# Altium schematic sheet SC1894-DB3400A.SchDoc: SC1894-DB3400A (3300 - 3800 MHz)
size B; Organization: Maxim Integrated; Address1: 160 Rio Robles; Address2: San Jose, CA. 95134; Address3: U.S.A.; Address4: 408-601-1000; Revision: 2.0; SheetNumber: 1; SheetTotal: 1; PageSetup: Record=PageOptions¦CenterHorizontal=True¦CenterVertical=True¦PrintScale=1.12¦XCorrection=1.00¦YCorrection=1.00¦PrintKind=1¦BorderSize=5000000¦LeftOffset=0¦BottomOffset=0¦Orientation=2¦PaperLength=1000¦PaperWidth=1000¦Scale=100¦PaperSource=15¦PrintQuality=600¦MediaType=1¦DitherType=10¦PaperKind=Tabloid¦PrintScaleMode=1
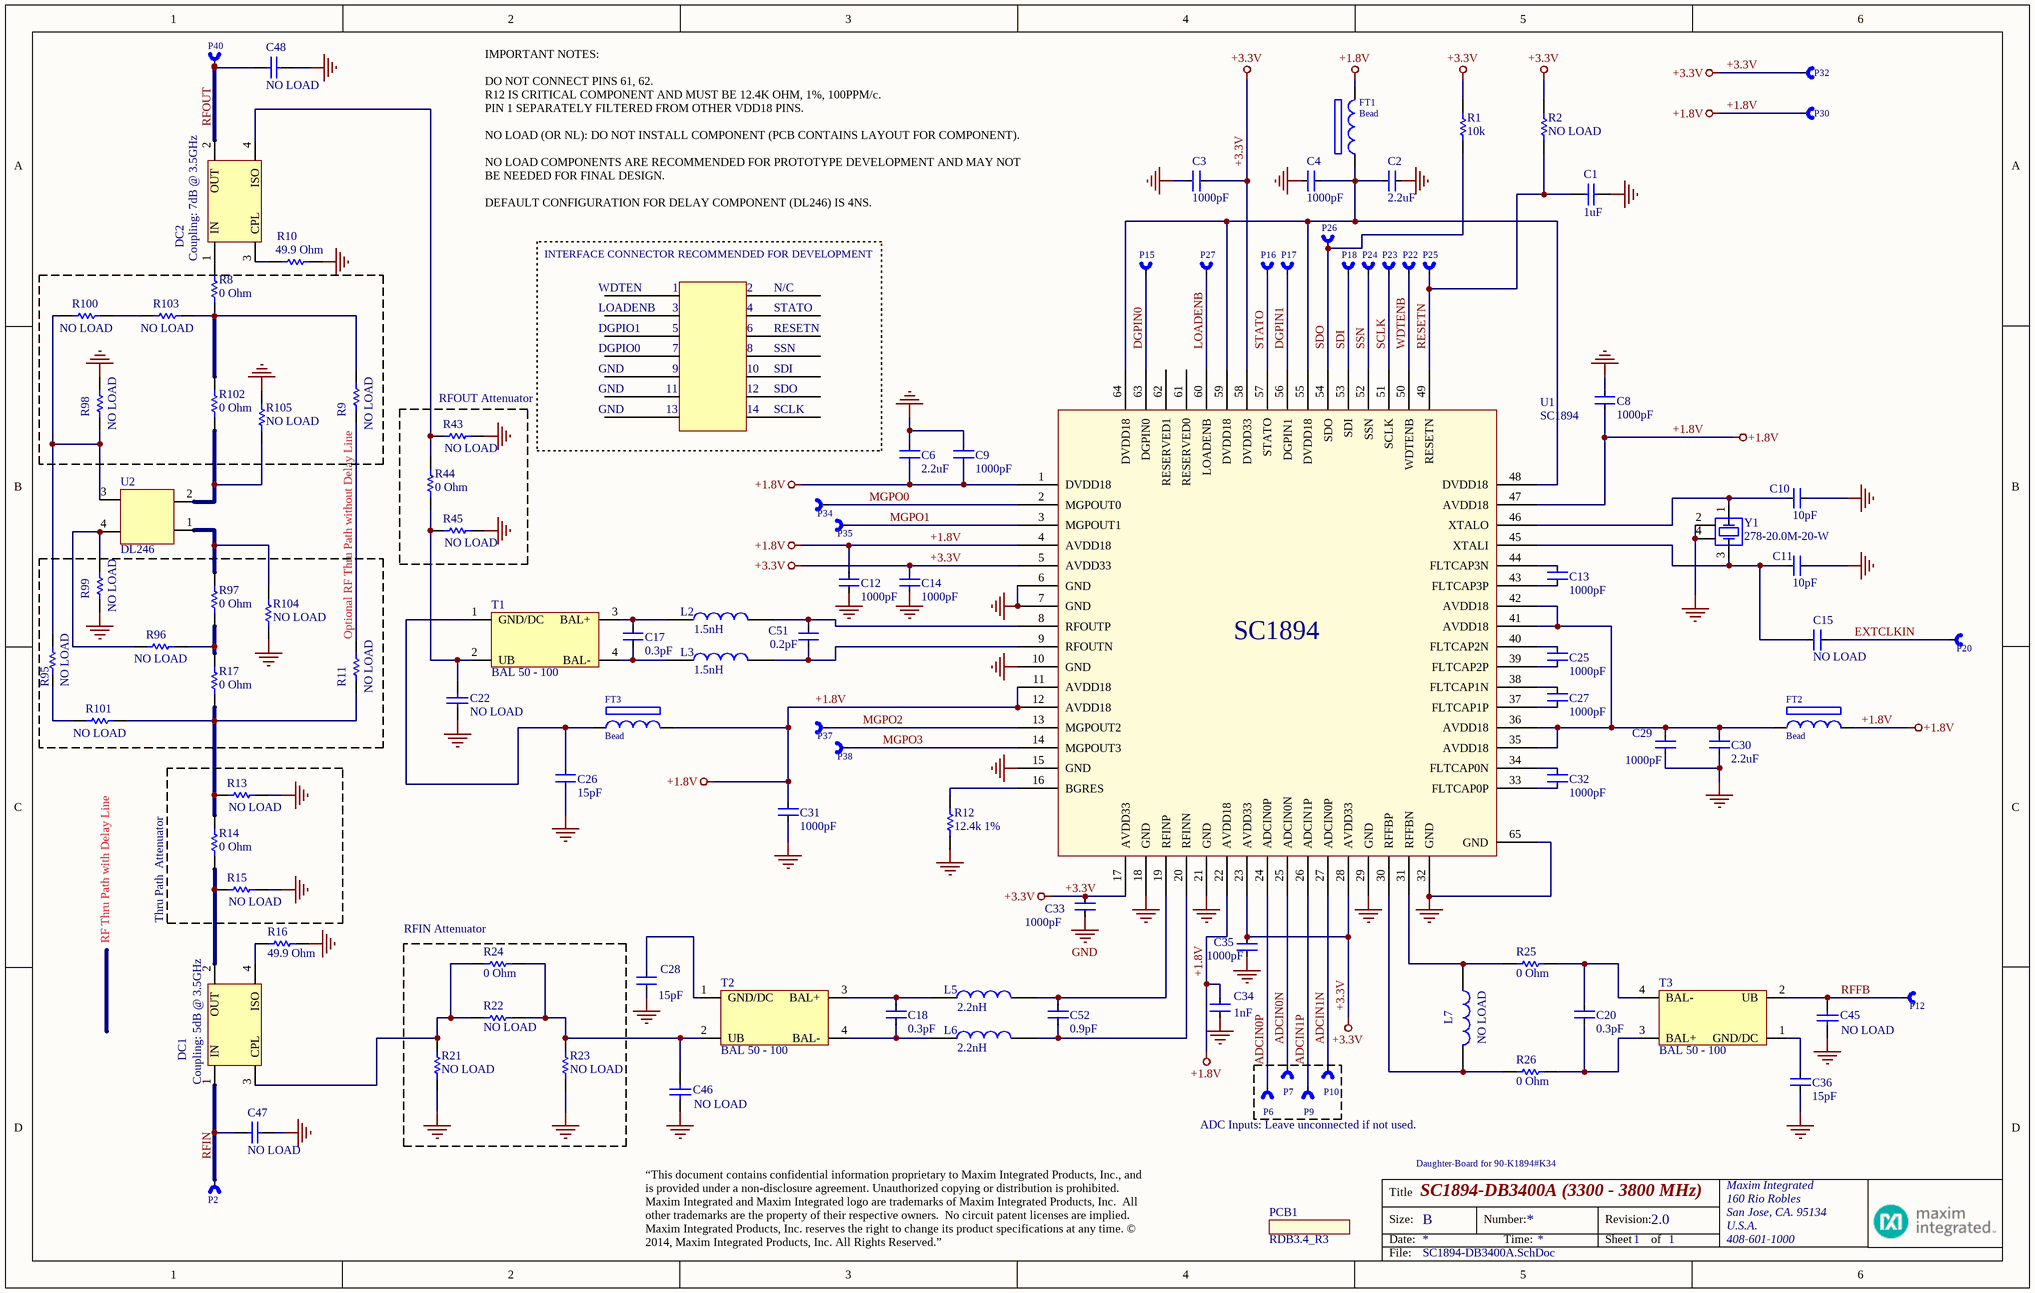
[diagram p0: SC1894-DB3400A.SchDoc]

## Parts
C1  1uF  [1608[0603]]
C2  2.2uF  [0603 SMD]
C3  1000pF  [0402 SMD]
C4  1000pF  [0402 SMD]
C6  2.2uF  [0603 SMD]
C8  1000pF  [0402 SMD]
C9  1000pF  [0402 SMD]
C10  10pF  [0402 SMD]
C11  10pF  [0402 SMD]
C12  1000pF  [0402 SMD]
C13  1000pF  [0402 SMD]
C14  1000pF  [0402 SMD]
C15  NO LOAD  [0402 SMD]
C17  0.3pF  [0402 SMD]
C18  0.3pF  [0402 SMD]
C20  0.3pF  [0402 SMD]
C22  NO LOAD  [0402 SMD]
C25  1000pF  [0402 SMD]
C26  15pF  [0402 SMD]
C27  1000pF  [0402 SMD]
C28  15pF  [0402 SMD]
C29  1000pF  [0402 SMD]
C30  2.2uF  [0603 SMD]
C31  1000pF  [0402 SMD]
C32  1000pF  [0402 SMD]
C33  1000pF  [0402 SMD]
C34  1nF  [0402 SMD]
C35  1000pF  [0402 SMD]
C36  15pF  [0402 SMD]
C45  NO LOAD  [0402 SMD]
C46  NO LOAD  [0402 SMD]
C47  NO LOAD  [0402 SMD]
C48  NO LOAD  [0402 SMD]
C51  0.2pF  [0402 SMD]
C52  0.9pF  [0402 SMD]
DC1  Coupling: 5dB @ 3.5GHz  [0603_AVX_LGA_COUPLER]
DC2  Coupling: 7dB @ 3.5GHz  [0603_AVX_LGA_COUPLER]
FT1  Bead  [0603 SMD]
FT2  Bead  [0603 SMD]
FT3  Bead  [0402 SMD]
L2  1.5nH  [0402 SMD]
L3  1.5nH  [0402 SMD]
L5  2.2nH  [0402 SMD]
L6  2.2nH  [0402 SMD]
L7  NO LOAD  [0402 SMD]
P2  PORT 1-M  [PORT-1_M-PAD]  (value not drawn)
P6  PORT 1-M  [PORT-1_M-PAD]  (value not drawn)
P7  PORT 1-M  [PORT-1_M-PAD]  (value not drawn)
P9  PORT 1-M  [PORT-1_M-PAD]  (value not drawn)
P10  PORT 1-M  [PORT-1_M-PAD]  (value not drawn)
P12  PORT 1-M  [PORT-1_M-PAD]  (value not drawn)
P15  PORT 1-M  [PORT-1_M-PAD]  (value not drawn)
P16  PORT 1-M  [PORT-1_M-PAD]  (value not drawn)
P17  PORT 1-M  [PORT-1_M-PAD]  (value not drawn)
P18  PORT 1-M  [PORT-1_M-PAD]  (value not drawn)
P20  PORT 1-M  [PORT-1_M-PAD]  (value not drawn)
P22  PORT 1-M  [PORT-1_M-PAD]  (value not drawn)
P23  PORT 1-M  [PORT-1_M-PAD]  (value not drawn)
P24  PORT 1-M  [PORT-1_M-PAD]  (value not drawn)
P25  PORT 1-M  [PORT-1_M-PAD]  (value not drawn)
P26  PORT 1-M  [PORT-1_M-PAD]  (value not drawn)
P27  PORT 1-M  [PORT-1_M-PAD]  (value not drawn)
P30  PORT 1-M  [PORT-1_M-PAD]  (value not drawn)
P32  PORT 1-M  [PORT-1_M-PAD]  (value not drawn)
P34  PORT 1-M  [PORT-1_M-PAD]  (value not drawn)
P35  PORT 1-M  [PORT-1_M-PAD]  (value not drawn)
P37  PORT 1-M  [PORT-1_M-PAD]  (value not drawn)
P38  PORT 1-M  [PORT-1_M-PAD]  (value not drawn)
P40  PORT 1-M  [PORT-1_M-PAD]  (value not drawn)
PCB1  RDB3.4_R3
R1  10k  [0402 SMD]
R2  NO LOAD  [0402 SMD]
R8  0 Ohm  [0402 SMD]
R9  NO LOAD  [0402 SMD]
R10  49.9 Ohm  [0402 SMD]
R11  NO LOAD  [0402 SMD]
R12  12.4k 1%  [0402 SMD]
R13  NO LOAD  [0402 SMD]
R14  0 Ohm  [0402 SMD]
R15  NO LOAD  [0402 SMD]
R16  49.9 Ohm  [0402 SMD]
R17  0 Ohm  [0402 SMD]
R21  NO LOAD  [0402 SMD]
R22  NO LOAD  [0201_SMT]
R23  NO LOAD  [0402 SMD]
R24  0 Ohm  [0201_SMT]
R25  0 Ohm  [0402 SMD]
R26  0 Ohm  [0402 SMD]
R43  NO LOAD  [0402 SMD]
R44  0 Ohm  [0402 SMD]
R45  NO LOAD  [0402 SMD]
R95  NO LOAD  [0402 SMD]
R96  NO LOAD  [0402 SMD]
R97  0 Ohm  [0402 SMD]
R98  NO LOAD  [0402 SMD]
R99  NO LOAD  [0402 SMD]
R100  NO LOAD  [0402 SMD]
R101  NO LOAD  [0402 SMD]
R102  0 Ohm  [0402 SMD]
R103  NO LOAD  [0402 SMD]
R104  NO LOAD  [0402 SMD]
R105  NO LOAD  [0402 SMD]
T1  BAL 50 - 100  [0404_Balun]
T2  BAL 50 - 100  [0404_Balun]
T3  BAL 50 - 100  [0404_Balun]
U1  SC1894  [SC1894]
U2  DL246  [DL246-A]
Y1  278-20.0M-20-W  [278-20.0M]

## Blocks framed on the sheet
RFOUT Attenuator: R43-R45
Optional RF Thru Path without Delay Line: R11 R17 R95-R97 R99 R101 R104
Thru Path  Attenuator: R13-R15
RFIN Attenuator: R21-R24

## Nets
+1.8V: C6.2 C8.2 C9.2 C12.1 C31.2 C34.2 FT1.2 FT2.2 FT3.2 P30.1(P*) U1.1(DVDD18) U1.4(AVDD18) U1.11(AVDD18) U1.12(AVDD18) U1.22(AVDD18) U1.47(AVDD18)
+3.3V: C3.2 C14.1 C33.1 C35.2 P32.1(P*) R1.2 R2.2 U1.5(AVDD33) U1.17(AVDD33) U1.23(AVDD33) U1.28(AVDD33) U1.58(DVDD33)
GND: C1.1 C2.2 C3.1 C4.1 C6.1 C8.1 C9.1 C10.2 C11.2 C12.2 C14.2 C22.1 C26.2 C28.2 C29.2 C30.2 C31.1 C33.2 C34.1 C35.1 C36.2 C45.1 C46.1 C47.1 C48.1 R10.2 R12.1 R13.2 R15.2 R16.2 R21.2 R23.2 R43.2 R45.2 R98.1 R99.2 R104.2 R105.1 U1.6(GND) U1.7(GND) U1.10(GND) U1.15(GND) U1.18(GND) U1.21(GND) U1.29(GND) U1.32(GND) U1.65(GND) Y1.2(SHIELD1) Y1.4(SHIELD2)
ADCIN0N: P7.1(P*) U1.25(ADCIN0N)
ADCIN0P: P6.1(P*) U1.24(ADCIN0P)
ADCIN1N: P10.1(P*) U1.27(ADCIN0P)
ADCIN1P: P9.1(P*) U1.26(ADCIN1P)
DGPIN0: P15.1(P*) U1.63(DGPIN0)
DGPIN1: P17.1(P*) U1.56(DGPIN1)
EXTCLKIN: C15.2 P20.1(P*)
LOADENB: P27.1(P*) U1.60(LOADENB)
MGPO0: P34.1(P*) U1.2(MGPOUT0)
MGPO1: P35.1(P*) U1.3(MGPOUT1)
MGPO2: P37.1(P*) U1.13(MGPOUT2)
MGPO3: P38.1(P*) U1.14(MGPOUT3)
RESETN: C1.2 P25.1(P*) R2.1 U1.49(RESETN)
RFFB: C45.2 P12.1(P*) T3.2(UB)
RFIN: C47.2 DC1.1(IN) P2.1(P*)
RFOUT: C48.2 DC2.2(OUT) P40.1(P*)
SCLK: P23.1(P*) U1.51(SCLK)
SDI: P18.1(P*) U1.53(SDI)
SDO: P26.1(P*) R1.1 U1.54(SDO)
SSN: P24.1(P*) U1.52(SSN)
STATO: P16.1(P*) U1.57(STATO)
WDTENB: P22.1(P*) U1.50(WDTENB)
NetC2_1: C2.1 C4.2 FT1.1 U1.48(DVDD18) U1.55(DVDD18) U1.59(DVDD18) U1.64(DVDD18)
NetC10_1: C10.1 U1.46(XTALO) Y1.1(OSC1)
NetC11_1: C11.1 C15.1 U1.45(XTALI) Y1.3(OSC2)
NetC13_1: C13.1 U1.44(FLTCAP3N)
NetC13_2: C13.2 U1.43(FLTCAP3P)
NetC17_1: C17.1 L2.1 T1.3(BAL+)
NetC17_2: C17.2 L3.1 T1.4(BAL-)
NetC18_1: C18.1 L5.1 T2.3(BAL+)
NetC18_2: C18.2 L6.1 T2.4(BAL-)
NetC20_1: C20.1 R25.2 T3.4(BAL-)
NetC20_2: C20.2 R26.2 T3.3(BAL+)
NetC22_2: C22.2 R44.1 R45.1 T1.2(UB)
NetC25_1: C25.1 U1.40(FLTCAP2N)
NetC25_2: C25.2 U1.39(FLTCAP2P)
NetC26_1: C26.1 FT3.1 T1.1(GND/DC)
NetC27_1: C27.1 U1.38(FLTCAP1N)
NetC27_2: C27.2 U1.37(FLTCAP1P)
NetC28_1: C28.1 T2.1(GND/DC)
NetC29_1: C29.1 C30.1 FT2.1 U1.35(AVDD18) U1.36(AVDD18) U1.41(AVDD18) U1.42(AVDD18)
NetC32_1: C32.1 U1.34(FLTCAP0N)
NetC32_2: C32.2 U1.33(FLTCAP0P)
NetC36_1: C36.1 T3.1(GND/DC)
NetC46_2: C46.2 R22.2 R23.1 R24.2 T2.2(UB)
NetC51_1: C51.1 L2.2 U1.8(RFOUTP)
NetC51_2: C51.2 L3.2 U1.9(RFOUTN)
NetC52_1: C52.1 L5.2 U1.19(RFINP)
NetC52_2: C52.2 L6.2 U1.20(RFINN)
NetDC1_2: DC1.2(OUT) R14.1 R15.1
NetDC1_3: DC1.3(CPL) R21.1 R22.1 R24.1
NetDC1_4: DC1.4(ISO) R16.1
NetDC2_1: DC2.1(IN) R8.2
NetDC2_3: DC2.3(CPL) R10.1
NetDC2_4: DC2.4(ISO) R43.1 R44.2
NetL7_1: L7.1 R25.1 U1.31(RFFBN)
NetL7_2: L7.2 R26.1 U1.30(RFFBP)
NetR8_1: R8.1 R9.2 R102.2 R103.2
NetR9_1: R9.1 R11.2
NetR11_1: R11.1 R13.1 R14.2 R17.1 R101.1
NetR12_2: R12.2 U1.16(BGRES)
NetR17_2: R17.2 R96.1 R97.1
NetR95_1: R95.1 R98.2 R100.1 U2.3(2ns_B)
NetR95_2: R95.2 R101.2
NetR96_2: R96.2 R99.1 U2.4(2ns_A)
NetR97_2: R97.2 R104.1 U2.1(4ns_A)
NetR100_2: R100.2 R103.1
NetR102_1: R102.1 R105.2 U2.2(4ns_B)

Not connected (* = marked no-connect by the designer): U1 61(RESERVED0) 62(RESERVED1)

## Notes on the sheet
- IMPORTANT NOTES:
  DO NOT CONNECT PINS 61, 62.
  R12 IS CRITICAL COMPONENT AND MUST BE 12.4K OHM, 1%, 100PPM/c.
  PIN 1 SEPARATELY FILTERED FROM OTHER VDD18 PINS.
  NO LOAD (OR NL): DO NOT INSTALL COMPONENT (PCB CONTAINS LAYOUT FOR COMPONENT).
  NO LOAD COMPONENTS ARE RECOMMENDED FOR PROTOTYPE DEVELOPMENT AND MAY NOT BE NEEDED FOR FINAL DESIGN.
  DEFAULT CONFIGURATION FOR DELAY COMPONENT (DL246) IS 4NS.
- INTERFACE CONNECTOR RECOMMENDED FOR DEVELOPMENT
- WDTEN
- 1
- 2
- N/C
- LOADENB
- DGPIO1
- DGPIO0
- GND
- 3
- 5
- 7
- 9
- 4
- 6
- 8
- 10
- STATO
- RESETN
- SSN
- SDI
- 11
- 13
- 12
- 14
- SDO
- SCLK
- (near R101) RF Thru Path with Delay Line
- ADC Inputs: Leave unconnected if not used.
- Daughter-Board for 90-K1894#K34
- “This document contains confidential information proprietary to Maxim Integrated Products, Inc., and is provided under a non-disclosure agreement. Unauthorized copying or distribution is prohibited.  Maxim Integrated and Maxim Integrated logo are trademarks of Maxim Integrated Products, Inc.  All other trademarks are the property of their respective owners.  No circuit patent licenses are implied.  Maxim Integrated Products, Inc. reserves the right to change its product specifications at any time. © 2014, Maxim Integrated Products, Inc. All Rights Reserved.”

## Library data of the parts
C1 = 1u: 1uF 0603 ceramic capacitor
C2 C6 C30 = Cap 2.2uF 0603: 2.2uF 0603
C3 C4 C8 C9 C12-C14 C25 C27 C29 C31-C35 = Cap 1000pF: 1000pF 0402
C10 C11 C15 = Cap 10pF: 10pF 0402
C17 C18 C20 = Cap 0.3pF: 0.3pF 0402; Part Substitution Allowed?: No
C22 C45-C48 = Capacitor: Generic Capacitor
C26 C28 C36 = Cap 15pF: 15pF 0402; Part Substitution Allowed?: No
C51 = Cap 0.2pF: 0.2pF 0402; Part Substitution Allowed?: No
C52 = Cap 0.9pF: 0.9pF 0402; Part Substitution Allowed?: No
DC1 = CP0603AxxxxCN: AVX 0603 Coupler C LGA Terminatioon
DC2 = CP0603AxxxxHN: AVX 0603 Coupler C LGA Terminatioon
FT1 FT2 = Bead 0603: Part Substitution Allowed?: No; Value: 120mH
FT3 = Bead 0402: Bead 0402 470 ohm; Part Substitution Allowed?: No; Value: 470mH
L2 L3 = 1.5nH: Part Substitution Allowed?: No
L5 L6 = 2.2nH: Part Substitution Allowed?: No
L7 = Inductor: SMT Inductor
P2 P6 P7 P9 P10 P12 P15-P18 P20 P22-P27 P30 P32 P34 P35 P37 P38 P40 = PORT 1-M: Ports of RDB Daughterboards
PCB1 = RDB3.4_R3: Printed Circuit Board (RDB3.4_R3)
R1 = 10k Ohm: 10k Ohm 0402
R2 = RES NL 0402: NO LOAD RESISTOR 0402
R8 = 0 Ohm: 0 Ohm 0402
R9 R11 R13 R15 R21 R23 R43 R45 R95 R96 R98-R101 R103-R105 = Resistor: Resistor Generic
R10 R16 = 49.9 Ohm 0402
R12 = 12.4k Ohm 0402
R14 R17 R25 R26 R44 R97 R102 = 0 Ohm 0402
R22 = RES NL 0201: NO LOAD RESISTOR 0201
R24 = 0 Ohm 0201
T1-T3 = BD3150N50100A00: Anaren 3100 - 5000 MHz 50Ohm UnBal - 100 Dif Balun; Part Substitution Allowed?: No
U1 = SC1894: SC1894: Adaptive RF Power Amplifier Linearizer; Manufacturer 1: Scintera; Manufacturer Part Number 1: SC1894A-00A00
U2 = DL246: Kyocera Delay Line DL246
Y1 = 278-20.0M-20-W: Crystal 20MHz 278-20.0M-20-W; Manufacturer 1: Oscilent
